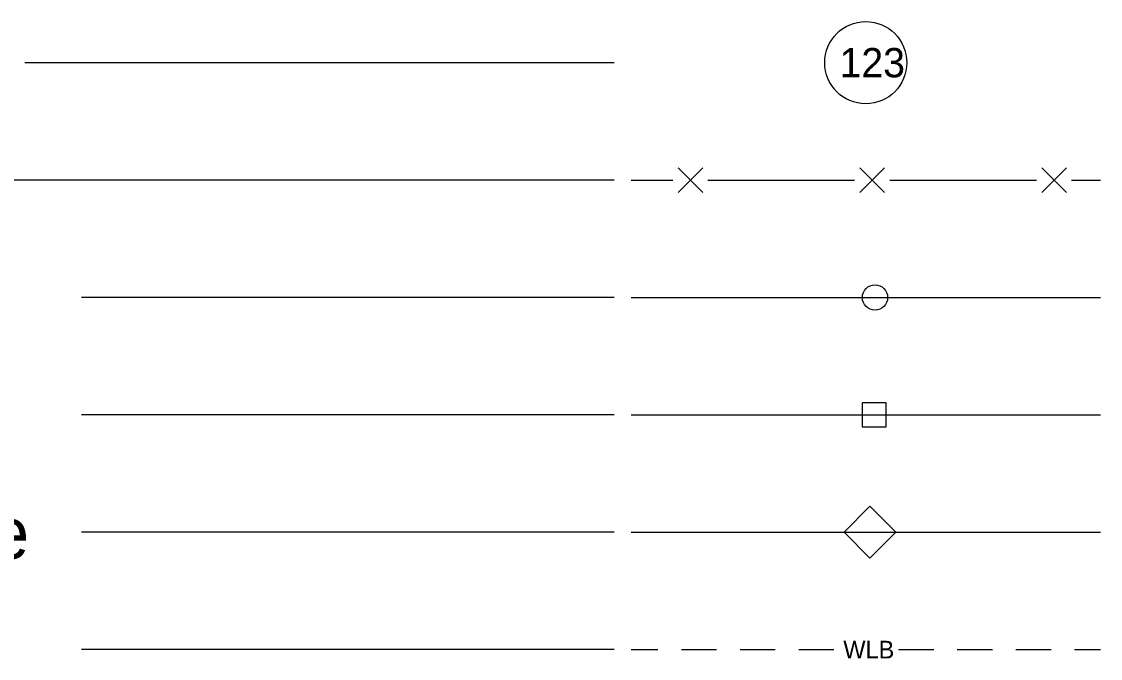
# Model space of a CAD drawing. Extents: x 1855058 to 1858918, y 1540202 to 1542502.
# Drawn here: x 1857333.4 to 1857518.9, y 1542110.6 to 1542220.1 of the extents above; entities that cross this region are included whole.
import ezdxf

# ---------------------------------------------------------------- set-up
doc = ezdxf.new("R2010")
doc.units = 0
doc.layers.add('Sheet Data Field CELL', color=7, linetype='Continuous')

msp = doc.modelspace()

# ---------------------------------------------------------------- linework, layer by layer
at = {"layer": 'Sheet Data Field CELL'}
for p, q in [((1857435.28, 1542212.99), (1857333.9, 1542212.99)), ((1857446.25, 1542190.69), (1857450.49, 1542194.93)), ((1857450.49, 1542190.69), (1857446.25, 1542194.93)), ((1857477.53, 1542190.69), (1857481.77, 1542194.93)), ((1857481.77, 1542190.69), (1857477.53, 1542194.93)), ((1857508.81, 1542190.69), (1857513.05, 1542194.93)), ((1857513.05, 1542190.69), (1857508.81, 1542194.93)), ((1857435.28, 1542192.81), (1857288.87, 1542192.81)), ((1857438.18, 1542192.81), (1857445.35, 1542192.81)), ((1857451.4, 1542192.81), (1857464.01, 1542192.81)), ((1857464.01, 1542192.81), (1857476.62, 1542192.81)), ((1857482.68, 1542192.81), (1857495.29, 1542192.81)), ((1857495.29, 1542192.81), (1857507.9, 1542192.81)), ((1857513.95, 1542192.81), (1857518.9, 1542192.81)), ((1857435.28, 1542172.63), (1857343.63, 1542172.63)), ((1857438.18, 1542172.63), (1857518.9, 1542172.63)), ((1857438.18, 1542172.63), (1857518.9, 1542172.63)), ((1857435.28, 1542152.45), (1857343.63, 1542152.45)), ((1857438.18, 1542152.45), (1857518.9, 1542152.45)), ((1857438.18, 1542152.45), (1857518.9, 1542152.45)), ((1857435.28, 1542132.28), (1857343.63, 1542132.28)), ((1857438.18, 1542132.28), (1857518.9, 1542132.28)), ((1857438.18, 1542132.28), (1857518.9, 1542132.28)), ((1857435.28, 1542112.1), (1857343.63, 1542112.1)), ((1857438.18, 1542112.1), (1857442.8, 1542112.1)), ((1857446.84, 1542112.1), (1857452.89, 1542112.1)), ((1857456.92, 1542112.1), (1857462.98, 1542112.1)), ((1857467.01, 1542112.1), (1857473.07, 1542112.1)), ((1857484.17, 1542112.1), (1857490.22, 1542112.1)), ((1857494.26, 1542112.1), (1857500.31, 1542112.1)), ((1857504.34, 1542112.1), (1857510.4, 1542112.1)), ((1857514.43, 1542112.1), (1857518.9, 1542112.1))]:
    msp.add_line(p, q, dxfattribs=at)
for points in [[(1857477.91, 1542150.39), (1857482.05, 1542150.39), (1857482.05, 1542154.52), (1857477.91, 1542154.52)], [(1857479.25, 1542127.84), (1857483.69, 1542132.28), (1857479.25, 1542136.77), (1857474.81, 1542132.28)]]:
    msp.add_lwpolyline(points, close=True, dxfattribs=at)
for centre, radius in [((1857478.54, 1542212.99), 7.06), ((1857480.13, 1542172.63), 2.17)]:
    msp.add_circle(centre, radius, dxfattribs=at)

# ---------------------------------------------------------------- texts
for s, height, p in [('123', 5.045, (1857474.03, 1542210.47)), ('Proposed Barbed Wire Fence', 8.8282, (1857179.14, 1542127.7)), ('WLB', 3.027, (1857474.68, 1542110.58))]:
    msp.add_text(s, height=height, dxfattribs=at).set_placement(p)

doc.saveas('drawing.dxf')
